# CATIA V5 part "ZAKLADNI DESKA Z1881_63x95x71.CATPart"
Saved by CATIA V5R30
Part number: ZAKLADNI DESKA MENSI
Bounding box of the stored display mesh (mm): x 0 to 71, y 0 to 12, z -47.5 to 47.5
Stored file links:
  C:\Users\ondra\Desktop\PŘÍLOHA P III\CATIA\ZAKLADNI DESKA Z1881_63x95x71.CATPart
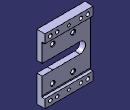
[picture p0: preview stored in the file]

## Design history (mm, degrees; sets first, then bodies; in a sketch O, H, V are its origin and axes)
Set1
  DatumSurface1 to DatumSurface58 "Z1881/63"
  Plane1: type Tangent, Support DatumSurface57, RefPoint vertex [face of DatumSurface57]
  Plane2: type Tangent, Support DatumSurface50, RefPoint vertex [face of DatumSurface57]
  Plane3: type Tangent, Support DatumSurface54, RefPoint vertex [face of DatumSurface57]
  Plane4: type Tangent, Support DatumSurface55, RefPoint vertex [face of DatumSurface57]
  Plane5: type Tangent, Support DatumSurface57, RefPoint vertex [face of DatumSurface57]
  Plane6: type Tangent, Support DatumSurface49, RefPoint vertex [face of DatumSurface57]
  Join1: Elements (DatumSurface1; DatumSurface2; DatumSurface3; DatumSurface4; DatumSurface5; DatumSurface6; DatumSurface7; DatumSurface8; DatumSurface9; DatumSurface10; DatumSurface11; DatumSurface12; DatumSurface13; DatumSurface14; DatumSurface15; DatumSurface16; DatumSurface17; DatumSurface18; DatumSurface19; DatumSurface20; DatumSurface21; DatumSurface22; DatumSurface23; DatumSurface24; DatumSurface25; DatumSurface26; DatumSurface27; DatumSurface28; DatumSurface29; DatumSurface30; DatumSurface31; DatumSurface32; DatumSurface33; DatumSurface34; DatumSurface35; DatumSurface36; DatumSurface37; DatumSurface38; DatumSurface39; DatumSurface40; DatumSurface41; DatumSurface42; DatumSurface43; DatumSurface44; DatumSurface45; DatumSurface46; DatumSurface47; DatumSurface48; DatumSurface49; DatumSurface50; DatumSurface51; DatumSurface52; DatumSurface53; DatumSurface54; DatumSurface55; DatumSurface56; DatumSurface57; DatumSurface58)
Body1 (main body)
  CloseSurface1: CloseElement Join1
  Sketch1 on zx-plane, origin (0, 0, 0), H (-1, 0, 0), V (0, 0, 1)
    reference projected line E2 (-15.5, 8) -> (-55.5, 8) from edge [face of CloseSurface1 | face of CloseSurface1]
    reference projected line E3 (-71, 33) -> (-71, -33) from edge [face of CloseSurface1 | face of CloseSurface1]
    line L1 (-55.5, -8) -> (-71, -8)
    line L2 (-71, -8) -> (-71, 8)
    line L3 (-71, 8) -> (-55.5, 8)
    line L4 (-55.5, 8) -> (-55.5, -8)
    point P8 (-71, 8)
    horizontal: L1 H, L3 H
    vertical: L2 V, L4 V
    coincidence: P8 E3, P8 E2
  Pocket1: profile Sketch1, direction (0, -1, 0), through (limit type 6)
